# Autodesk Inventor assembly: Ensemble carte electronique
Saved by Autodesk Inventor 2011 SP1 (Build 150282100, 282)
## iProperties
Created: 2010-12
Part Number: Ensemble carte electronique
Document SubType Name: Assembly
Designer: eric
Author: eric
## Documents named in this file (4)
- D:\eduinventor\maquettesaip2011\machineàpain\Workspace\Ensemble carte electronique.iam
- D:\eduinventor\maquettesaip2011\machineàpain\Workspace\equerre de carte electronique.ipt
- D:\eduinventor\maquettesaip2011\machineàpain\Workspace\transformateur.ipt
- D:\eduinventor\maquettesaip2011\machineàpain\Workspace\Carte électronique basse.iam
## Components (3 placed, 3 different names)
1. equerre de carte electronique:1
2. transformateur:1
3. Carte électronique basse:1 [sub-assembly]
